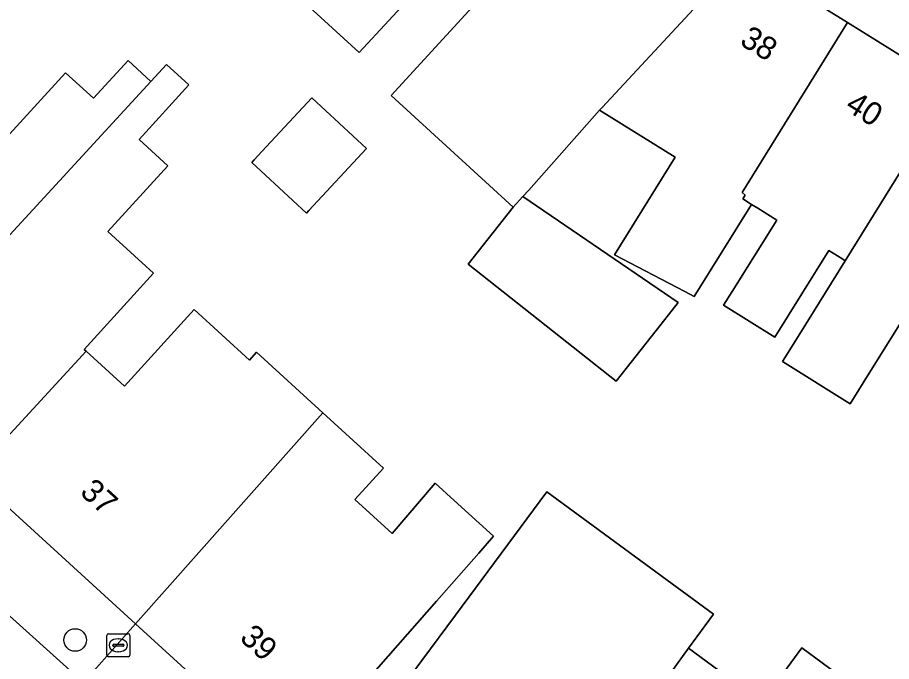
# Model space of a CAD drawing. Extents: x 160663 to 161506, y 382245 to 383291.
# Drawn here: x 160958.95 to 160996.83, y 383092.19 to 383120.11 of the extents above; entities that cross this region are included whole.
import ezdxf

# ---------------------------------------------------------------- set-up
doc = ezdxf.new("R2010")
doc.units = 0
for name, color, linetype in [('IMGEO_Boom', 7, 'Continuous'), ('IMGEO_Brandkraan', 7, 'Continuous'), ('IMGEO_Erf', 7, 'Continuous'), ('IMGEO_Pand', 7, 'Continuous'), ('IMGEO_Pand_nummerreeks', 7, 'Continuous'), ('IMGEO_Rijbaan_lokaal_open', 7, 'Continuous'), ('IMGEO_Voetpad_open', 7, 'Continuous')]:
    doc.layers.add(name, color=color, linetype=linetype)

msp = doc.modelspace()

# ---------------------------------------------------------------- linework, layer by layer
at = {"layer": 'IMGEO_Boom'}
msp.add_circle((160961.446, 383093.127), 0.489, dxfattribs=at)
at = {"layer": 'IMGEO_Brandkraan'}
for p, q in [((160962.82, 383092.474), (160962.82, 383093.326)), ((160962.895, 383093.4), (160963.747, 383093.4)), ((160963.308, 383093.18), (160963.333, 383093.18)), ((160963.821, 383093.326), (160963.821, 383092.474)), ((160963.079, 383092.894), (160963.079, 383092.906)), ((160963.517, 383092.857), (160963.119, 383092.857)), ((160963.122, 383092.943), (160963.52, 383092.943)), ((160963.563, 383092.906), (160963.563, 383092.894)), ((160963.747, 383092.4), (160962.895, 383092.4)), ((160963.331, 383092.62), (160963.306, 383092.62))]:
    msp.add_line(p, q, dxfattribs=at)
for points in [[(160962.82, 383092.474), (160962.82, 383093.326)], [(160962.895, 383093.4), (160963.747, 383093.4)], [(160963.821, 383093.326), (160963.821, 383092.474)], [(160963.747, 383092.4), (160962.895, 383092.4)]]:
    msp.add_lwpolyline(points, dxfattribs=at)
for centre, radius, start, end in [((160962.897, 383093.324), 0.0765, 91.552, 178.448), ((160962.897, 383093.324), 0.0765, 91.552, 178.448), ((160963.745, 383093.324), 0.0765, 1.552, 88.448), ((160963.745, 383093.324), 0.0765, 1.552, 88.448), ((160963.119, 383092.903), 0.0403, 85.8775, 175.7526), ((160963.116, 383092.893), 0.0366, 178.938, 274.7102), ((160963.52, 383092.9), 0.043, 264.8664, 352.4533), ((160963.524, 383092.905), 0.0386, 1.7309, 96.639), ((160962.897, 383092.476), 0.0765, 181.552, 268.448), ((160962.897, 383092.476), 0.0765, 181.552, 268.448), ((160963.745, 383092.476), 0.0765, 271.552, 358.448), ((160963.745, 383092.476), 0.0765, 271.552, 358.448)]:
    msp.add_arc(centre, radius, start, end, dxfattribs=at)
for centre, major_axis, ratio, start_param, end_param in [((160963.307, 383092.9), (-0.387, 0.002), 0.722429, 4.712389, 7.853982), ((160963.332, 383092.9), (-0.39, 0.002), 0.717154, 1.570796, 4.712389)]:
    msp.add_ellipse(centre, major_axis=major_axis, ratio=ratio, start_param=start_param, end_param=end_param, dxfattribs=at)
at = {"layer": 'IMGEO_Erf'}
for points in [[(160977.622, 383122.768), (160973.756, 383118.596), (160971.427, 383120.722)], [(160997.766, 383107.741), (160995.798, 383104.581), (160995.045, 383103.372), (160992.114, 383105.196), (160992.866, 383106.407), (160994.829, 383109.57), (160994.674, 383109.666), (160994.113, 383110.016), (160991.777, 383106.254), (160989.558, 383107.636), (160989.931, 383108.235), (160991.859, 383111.33), (160991.035, 383111.844), (160990.767, 383112.011), (160988.28, 383108.017), (160987.878, 383108.228), (160984.829, 383109.829), (160987.458, 383114.051), (160984.179, 383116.092), (160981.109, 383112.629), (160980.854, 383112.349), (160987.589, 383107.754), (160986.846, 383106.814), (160984.901, 383104.355), (160978.487, 383109.426), (160980.441, 383111.897), (160975.148, 383116.727), (160979.942, 383121.982)], [(160958.601, 383115.05), (160961.033, 383117.715), (160962.245, 383116.609), (160963.742, 383118.25), (160964.733, 383117.338), (160965.411, 383118.074), (160966.382, 383117.188), (160964.219, 383114.818), (160965.464, 383113.681), (160962.866, 383110.834), (160964.849, 383109.024), (160961.841, 383105.727), (160961.927, 383105.649), (160963.583, 383104.138), (160966.605, 383107.45), (160969, 383105.264), (160969.31, 383105.603), (160972.183, 383102.981), (160974.817, 383100.578), (160973.578, 383099.22), (160975.197, 383097.743), (160977.06, 383099.923), (160977.883, 383099.173), (160979.58, 383097.624), (160978.949, 383096.897), (160977.109, 383094.805), (160970.827, 383087.655)], [(160975.35, 383090.71), (160976.476, 383092.233), (160977.929, 383094.199), (160981.889, 383099.555), (160989.111, 383094.252), (160988.034, 383092.771), (160991.206, 383090.426)], [(160991.553, 383090.895), (160992.95, 383092.785), (160995.318, 383091.034)]]:
    msp.add_lwpolyline(points, dxfattribs=at)
msp.add_lwpolyline([(160971.475, 383111.631), (160969.104, 383113.829), (160969.21, 383113.944), (160969.543, 383114.302), (160971.705, 383116.635), (160974.076, 383114.438), (160971.582, 383111.746)], close=True, dxfattribs=at)
at = {"layer": 'IMGEO_Pand'}
for points in [[(160982.237, 383127.799), (160977.131, 383130.978), (160972.189, 383125.552), (160974.178, 383123.736), (160971.427, 383120.722), (160973.756, 383118.596), (160977.622, 383122.768), (160978.298, 383123.505)], [(160990.343, 383122.744), (160982.237, 383127.799), (160978.298, 383123.505), (160979.942, 383121.982), (160975.148, 383116.727), (160980.441, 383111.897), (160980.854, 383112.349), (160981.109, 383112.629), (160984.179, 383116.092), (160984.288, 383116.215)], [(160994.931, 383119.893), (160990.343, 383122.744), (160984.288, 383116.215), (160984.179, 383116.092), (160987.458, 383114.051), (160984.829, 383109.829), (160987.878, 383108.228), (160988.28, 383108.017), (160990.767, 383112.011), (160990.386, 383112.249), (160990.488, 383112.413), (160990.366, 383112.525)], [(160999.48, 383117.061), (160994.931, 383119.893), (160990.366, 383112.525), (160990.488, 383112.413), (160990.386, 383112.249), (160990.767, 383112.011), (160991.035, 383111.844), (160991.859, 383111.33), (160989.931, 383108.235), (160989.558, 383107.636), (160991.777, 383106.254), (160994.113, 383110.016), (160994.674, 383109.666), (160994.829, 383109.57)], [(160964.733, 383117.338), (160963.742, 383118.25), (160962.245, 383116.609), (160961.033, 383117.715), (160958.601, 383115.05), (160956.465, 383116.999), (160954.513, 383114.855), (160948.39, 383108.129), (160952.66, 383104.233)], [(160964.849, 383109.024), (160962.866, 383110.834), (160965.464, 383113.681), (160964.219, 383114.818), (160966.382, 383117.188), (160965.411, 383118.074), (160964.733, 383117.338), (160952.66, 383104.233), (160956.981, 383100.29), (160961.927, 383105.649), (160961.841, 383105.727)], [(161004.038, 383114.222), (161000, 383116.737), (160999.48, 383117.061), (160994.829, 383109.57), (160992.866, 383106.407), (160992.114, 383105.196), (160995.045, 383103.372), (160995.798, 383104.581), (160997.766, 383107.741), (160999.388, 383106.731), (161000, 383107.717)], [(160969.104, 383113.829), (160971.475, 383111.631), (160971.582, 383111.746), (160974.076, 383114.438), (160971.705, 383116.635), (160969.543, 383114.302), (160969.21, 383113.944)], [(160980.854, 383112.349), (160980.441, 383111.897), (160978.487, 383109.426), (160984.901, 383104.355), (160986.846, 383106.814), (160987.589, 383107.754)], [(160972.183, 383102.981), (160969.31, 383105.603), (160969, 383105.264), (160966.605, 383107.45), (160963.583, 383104.138), (160961.927, 383105.649), (160956.981, 383100.29), (160964.067, 383093.823)], [(160978.949, 383096.897), (160979.58, 383097.624), (160977.883, 383099.173), (160977.06, 383099.923), (160975.197, 383097.743), (160973.578, 383099.22), (160974.817, 383100.578), (160972.183, 383102.981), (160964.067, 383093.823), (160970.827, 383087.655), (160977.109, 383094.805)], [(160986.99, 383091.335), (160988.034, 383092.771), (160989.111, 383094.252), (160981.889, 383099.555), (160977.929, 383094.199), (160976.476, 383092.233), (160975.35, 383090.71), (160972.377, 383086.689), (160979.655, 383081.345)], [(160995.318, 383091.034), (160992.95, 383092.785), (160991.553, 383090.895), (160991.371, 383090.649), (160991.206, 383090.426), (160988.034, 383092.771), (160986.99, 383091.335), (160979.655, 383081.345), (160985.256, 383077.232)]]:
    msp.add_lwpolyline(points, close=True, dxfattribs=at)
at = {"layer": 'IMGEO_Rijbaan_lokaal_open'}
msp.add_lwpolyline([(160961.813, 383091.279), (160954.192, 383098.131), (160953.926, 383098.37), (160951.306, 383095.631), (160951.524, 383095.414)], dxfattribs=at)
at = {"layer": 'IMGEO_Voetpad_open'}
for points in [[(160962.901, 383143.638), (160961.243, 383144.612), (160959.063, 383142.231), (160965.124, 383138.456), (160965.366, 383138.305), (160972.148, 383134.082), (160977.131, 383130.978), (160982.237, 383127.799), (160990.343, 383122.744), (160994.931, 383119.893), (160999.48, 383117.061), (161000, 383116.737), (161004.038, 383114.222), (161008.588, 383111.389), (161013.121, 383108.566), (161017.705, 383105.712), (161022.475, 383102.741), (161025.226, 383101.166), (161026.056, 383100.781), (161031.892, 383097.822), (161037.593, 383094.932), (161043.206, 383092.086)], [(160954.192, 383098.131), (160961.813, 383091.279), (160964.067, 383093.823), (160956.981, 383100.29), (160952.66, 383104.233), (160948.39, 383108.129), (160948.102, 383108.392), (160948.002, 383108.283), (160942.448, 383113.457), (160937.416, 383118.145), (160935.811, 383119.75), (160935.53, 383119.466), (160934.171, 383120.731), (160934.436, 383121.004), (160932.761, 383122.608), (160928.405, 383126.797), (160928.327, 383126.872), (160928.203, 383126.744), (160925.4, 383129.44), (160925.467, 383129.608), (160920.856, 383134.043), (160920.779, 383134.126), (160920.569, 383134.352), (160914.367, 383141.037)], [(160970.827, 383087.655), (160964.067, 383093.823), (160961.813, 383091.279), (160965.014, 383088.402)]]:
    msp.add_lwpolyline(points, dxfattribs=at)

# ---------------------------------------------------------------- texts
at = {"layer": 'IMGEO_Pand_nummerreeks'}
for s, rotation, p in [('38', 328.1493, (160990.207, 383118.966)), ('40', 328.0863, (160994.773, 383116.129)), ('37', 317.6189, (160961.612, 383099.475)), ('39', 317.6183, (160968.535, 383093.157))]:
    msp.add_text(s, height=1, rotation=rotation, dxfattribs=at).set_placement(p)

doc.saveas('drawing.dxf')
